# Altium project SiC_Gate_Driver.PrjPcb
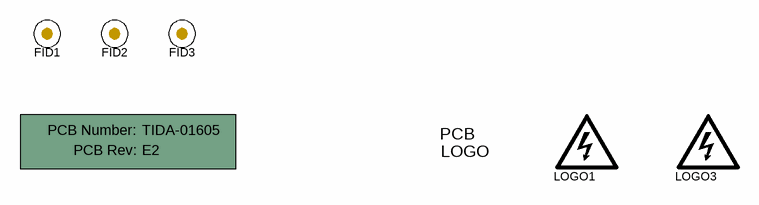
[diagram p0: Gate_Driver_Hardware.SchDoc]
CopyrightYear: 2019; PCB_Layout: X.Gong; PCB_Rev: E2; PRJ_Customer: Public Release; PRJ_Engineer: X.Gong; PRJ_Number: TIDA-01605; PRJ_Title: Isolated SiC Gate Driver with Soft Turn-off Protection; SCH_Rev: E2; TechSupport: http://www.ti.com/support; TID: TIDA-01605
2 sheets, 112 parts. Net scope: flat (ports and power ports of the same name join across sheets).
Board file: Gate_Driver.PcbDoc
Sheets:
  Gate_Driver_Hardware.SchDoc
  Gate_Driver.SchDoc

## Sheet Gate_Driver_Hardware.SchDoc
size 431 x 279 mm; Date: Not shown in title block; ApprovedBy: Not shown in title block; CheckedBy: Not shown in title block; Author: Not shown in title block; CompanyName: Not shown in title block; DrawnBy: G.Wang; Engineer: Not shown in title block; Organization: Not shown in title block; Address1: Not shown in title block; Address2: Not shown in title block; Address3: Not shown in title block; Address4: Not shown in title block; DocumentNumber: 1; Revision: Use project parameter SCH_Rev; SheetNumber: 3; SheetTotal: 3; PageSetup: Record=PageOptions¦CenterHorizontal=True¦CenterVertical=True¦PrintScale=1.00¦XCorrection=1.00¦YCorrection=1.00¦PrintKind=0¦BorderSize=5000000¦LeftOffset=0¦BottomOffset=0¦Orientation=2¦PaperLength=1000¦PaperWidth=1000¦Scale=100¦PaperSource=15¦PrintQuality=600¦MediaType=1¦DitherType=10¦PaperKind=Letter¦PrintScaleMode=1

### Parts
!PCB  Printed Circuit Board  (value not drawn)  (mechanical)
FID1  Fiducial  [Fiducial10-20]  (value not drawn)
FID2  Fiducial  [Fiducial10-20]  (value not drawn)
FID3  Fiducial  [Fiducial10-20]  (value not drawn)
LOGO1  DANGER HIGH VOLTAGE  [IEC_HighVoltage_Small]  (value not drawn)  (no BOM)
Logo2  Pb-Free Symbol  [Pb-Free_Overlay_Small]  (value not drawn)  (no BOM)
LOGO3  DANGER HIGH VOLTAGE  [IEC_HighVoltage_Small]  (value not drawn)  (no BOM)

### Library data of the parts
!PCB = PCB: Manufacturer: Any; PartNumber: TIDA-01605; SymbolCreator: a0412235
FID1-FID3 = Fiducial: Fiducial mark.  There is nothing to buy or mount.; SymbolCreator: codlsc
LOGO1 LOGO3 = IEC_HighVoltage: IEC 61010-1 High Voltage Warning; SymbolCreator: a0412235
Logo2 = Pb-Free: SymbolCreator: a0412235

## Sheet Gate_Driver.SchDoc
size 431 x 279 mm; Date: Not shown in title block; ApprovedBy: Not shown in title block; CheckedBy: Not shown in title block; Author: Not shown in title block; CompanyName: Not shown in title block; DrawnBy: G. Wang; Engineer: Not shown in title block; Organization: Not shown in title block; Address1: Not shown in title block; Address2: Not shown in title block; Address3: Not shown in title block; Address4: Not shown in title block; DocumentNumber: 1; Revision: Use project parameter SCH_Rev; SheetNumber: 2; SheetTotal: 3; PageSetup: Record=PageOptions¦CenterHorizontal=True¦CenterVertical=True¦PrintScale=1.00¦XCorrection=1.00¦YCorrection=1.00¦PrintKind=0¦BorderSize=5000000¦LeftOffset=0¦BottomOffset=0¦Orientation=2¦PaperLength=1000¦PaperWidth=1000¦Scale=100¦PaperSource=15¦PrintQuality=600¦MediaType=1¦DitherType=10¦PaperKind=Letter¦PrintScaleMode=1
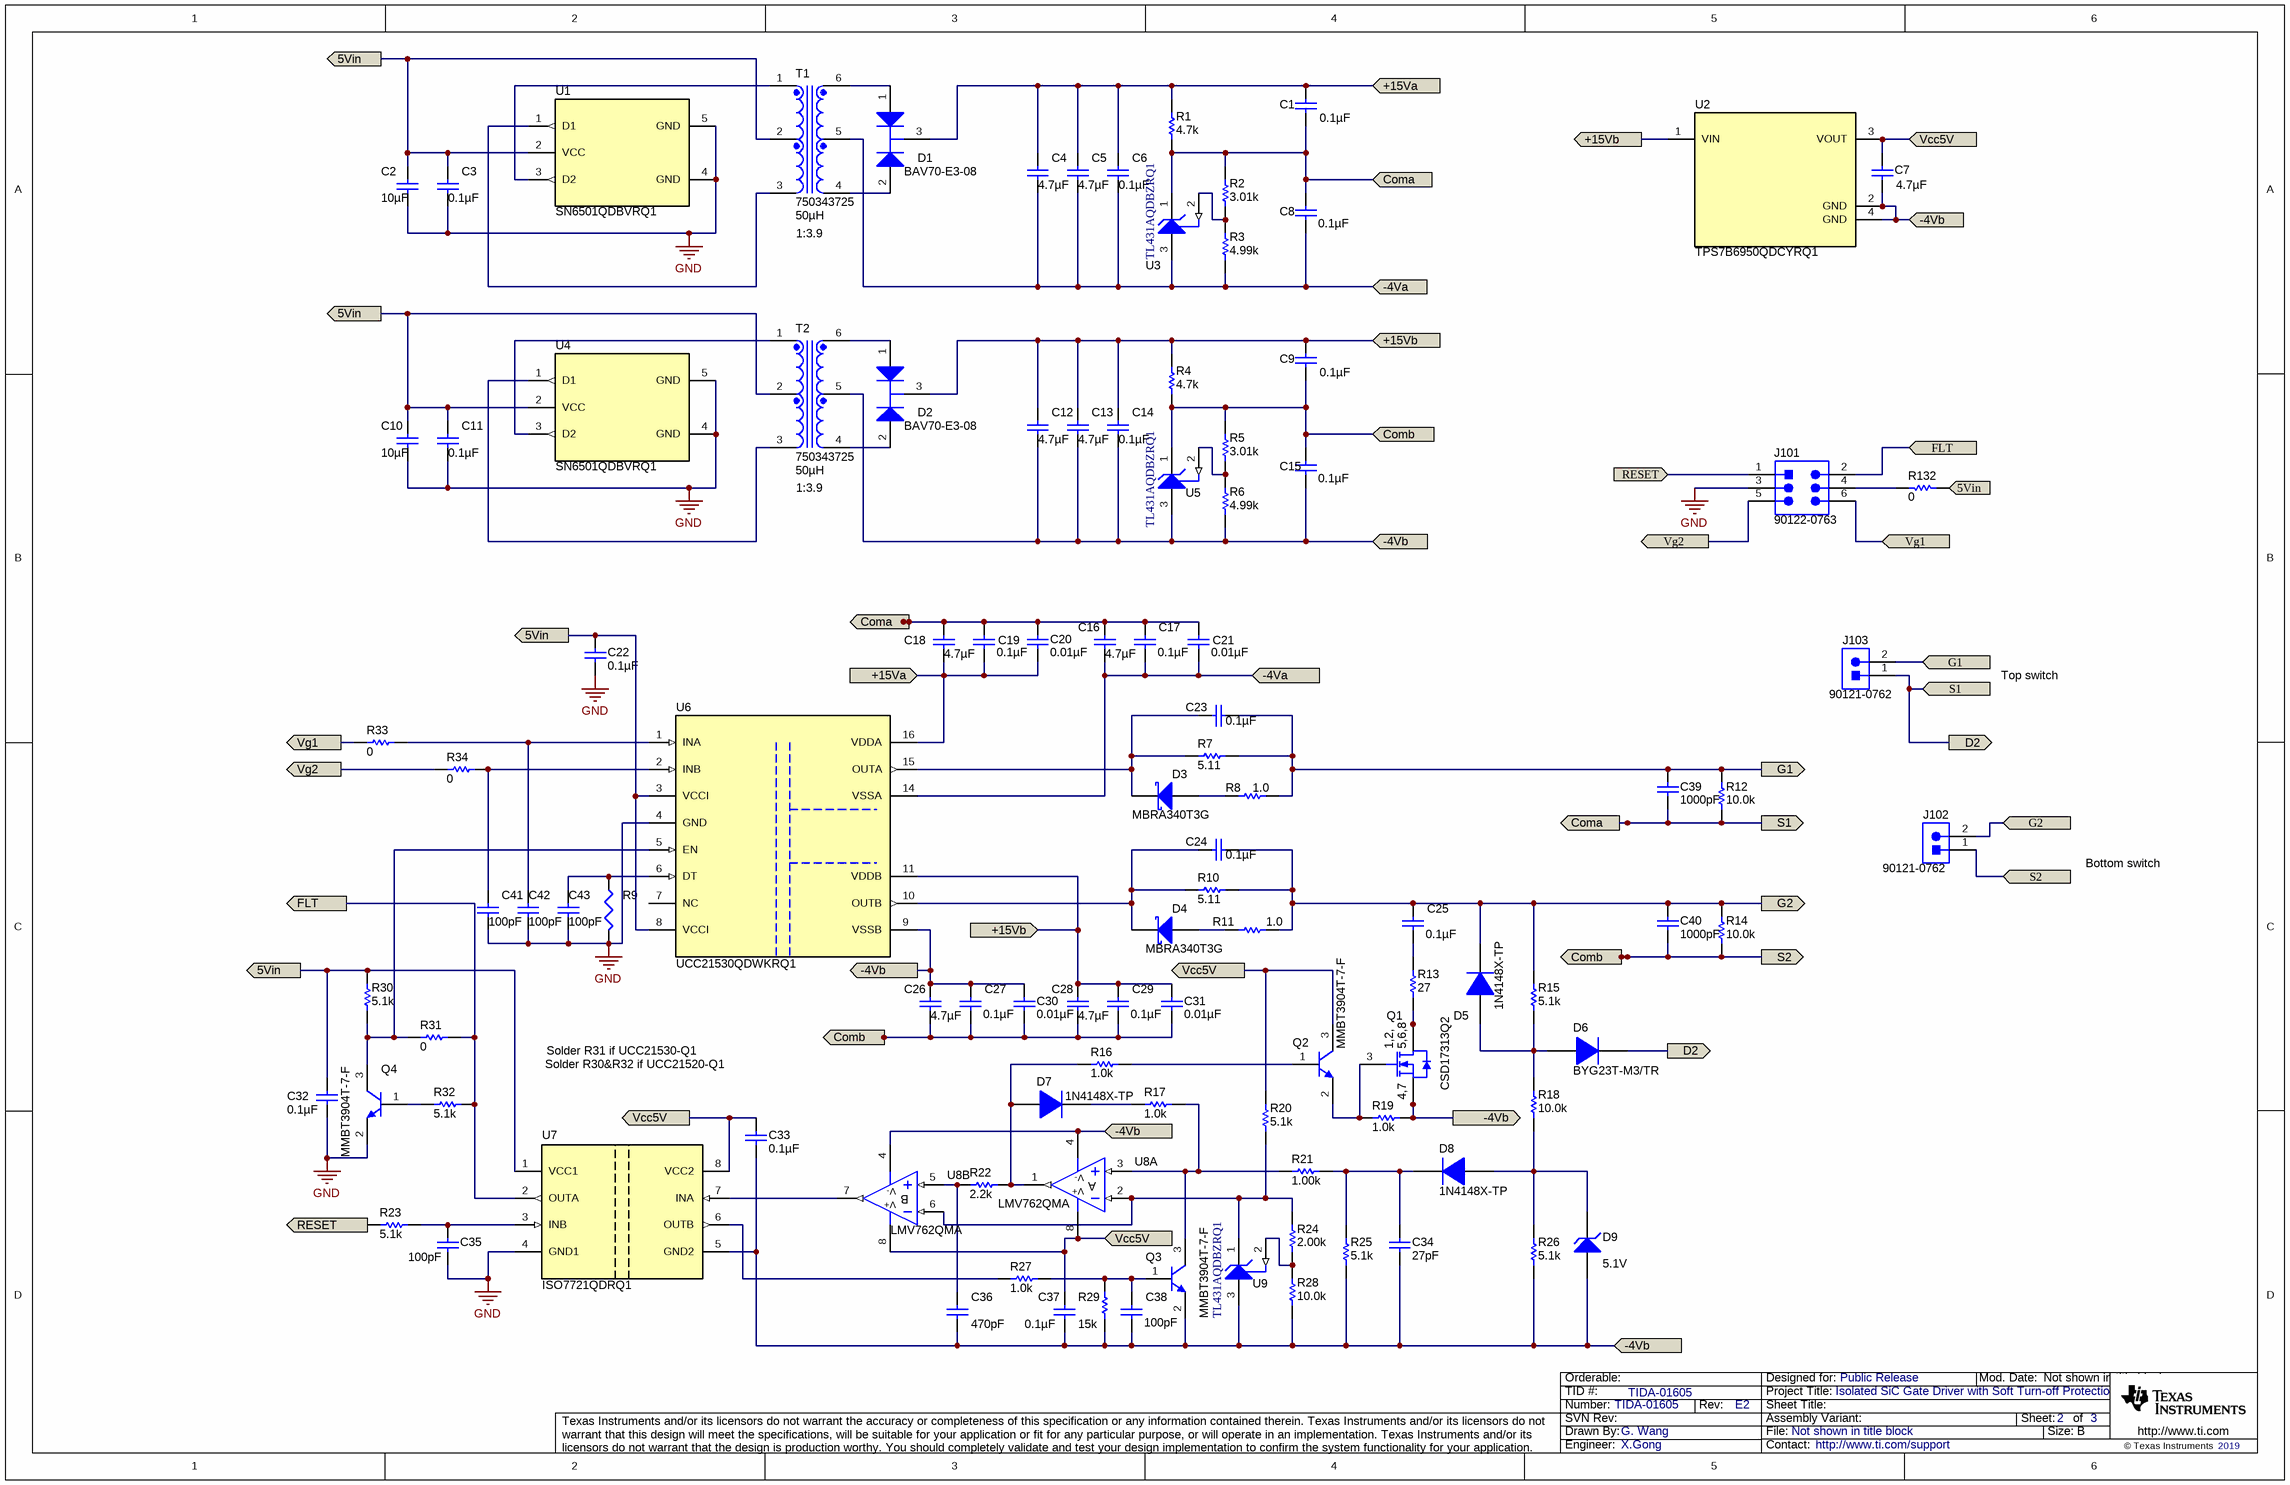
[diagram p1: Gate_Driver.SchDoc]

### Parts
C1  ValueDisplayed: 0.1µF  [0603]  (hidden comment: CGA3E2X7R1E104K080AA)
C2  ValueDisplayed: 10µF  [0603]  (hidden comment: GRT188C81A106ME13D)
C3  ValueDisplayed: 0.1µF  [0603]  (hidden comment: CGA3E2X7R1E104K080AA)
C4  ValueDisplayed: 4.7µF  [0805_HV]  (hidden comment: GRT21BR61H475KE13L)
C5  ValueDisplayed: 4.7µF  [0805_HV]  (hidden comment: GRT21BR61H475KE13L)
C6  ValueDisplayed: 0.1µF  [0603]  (hidden comment: CGA3E2X7R1E104K080AA)
C7  ValueDisplayed: 4.7µF  [0805_HV]  (hidden comment: GRT21BR61H475KE13L)
C8  ValueDisplayed: 0.1µF  [0603]  (hidden comment: CGA3E2X7R1E104K080AA)
C9  ValueDisplayed: 0.1µF  [0603]  (hidden comment: CGA3E2X7R1E104K080AA)
C10  ValueDisplayed: 10µF  [0603]  (hidden comment: GRT188C81A106ME13D)
C11  ValueDisplayed: 0.1µF  [0603]  (hidden comment: CGA3E2X7R1E104K080AA)
C12  ValueDisplayed: 4.7µF  [0805_HV]  (hidden comment: GRT21BR61H475KE13L)
C13  ValueDisplayed: 4.7µF  [0805_HV]  (hidden comment: GRT21BR61H475KE13L)
C14  ValueDisplayed: 0.1µF  [0603]  (hidden comment: CGA3E2X7R1E104K080AA)
C15  ValueDisplayed: 0.1µF  [0603]  (hidden comment: CGA3E2X7R1E104K080AA)
C16  ValueDisplayed: 4.7µF  [0805_HV]  (hidden comment: GRT21BR61H475KE13L)
C17  ValueDisplayed: 0.1µF  [0603]  (hidden comment: CGA3E2X7R1E104K080AA)
C18  ValueDisplayed: 4.7µF  [0805_HV]  (hidden comment: GRT21BR61H475KE13L)
C19  ValueDisplayed: 0.1µF  [0603]  (hidden comment: CGA3E2X7R1E104K080AA)
C20  ValueDisplayed: 0.01µF  [0603]  (hidden comment: CGA3E2C0G1H103J080AA)
C21  ValueDisplayed: 0.01µF  [0603]  (hidden comment: CGA3E2C0G1H103J080AA)
C22  ValueDisplayed: 0.1µF  [0603]  (hidden comment: CGA3E2X7R1E104K080AA)
C23  ValueDisplayed: 0.1µF  [0603]  (hidden comment: CGA3E2X7R1E104K080AA)
C24  ValueDisplayed: 0.1µF  [0603]  (hidden comment: CGA3E2X7R1E104K080AA)
C25  ValueDisplayed: 0.1µF  [0603]  (hidden comment: CGA3E2X7R1E104K080AA)
C26  ValueDisplayed: 4.7µF  [0805_HV]  (hidden comment: GRT21BR61H475KE13L)
C27  ValueDisplayed: 0.1µF  [0603]  (hidden comment: CGA3E2X7R1E104K080AA)
C28  ValueDisplayed: 4.7µF  [0805_HV]  (hidden comment: GRT21BR61H475KE13L)
C29  ValueDisplayed: 0.1µF  [0603]  (hidden comment: CGA3E2X7R1E104K080AA)
C30  ValueDisplayed: 0.01µF  [0603]  (hidden comment: CGA3E2C0G1H103J080AA)
C31  ValueDisplayed: 0.01µF  [0603]  (hidden comment: CGA3E2C0G1H103J080AA)
C32  ValueDisplayed: 0.1µF  [0603]  (hidden comment: CGA3E2X7R1E104K080AA)
C33  ValueDisplayed: 0.1µF  [0603]  (hidden comment: CGA3E2X7R1E104K080AA)
C34  ValueDisplayed: 27pF  [0402]  (hidden comment: GRM1555C1H270JA01D)
C35  ValueDisplayed: 100pF  [0603]  (hidden comment: CGA3E2NP01H101J080AA)
C36  ValueDisplayed: 470pF  [0603]  (hidden comment: GCM1885C1H471JA16D)
C37  ValueDisplayed: 0.1µF  [0603]  (hidden comment: CGA3E2X7R1E104K080AA)
C38  ValueDisplayed: 100pF  [0603]  (hidden comment: GCM1885C2A101JA16D)
C39  ValueDisplayed: 1000pF  [0402]  (hidden comment: GCM155R71H102KA37D)
C40  ValueDisplayed: 1000pF  [0402]  (hidden comment: GCM155R71H102KA37D)
C41  ValueDisplayed: 100pF  [0603]  (hidden comment: GCM1885C2A101JA16D)
C42  ValueDisplayed: 100pF  [0603]  (hidden comment: GCM1885C2A101JA16D)
C43  ValueDisplayed: 100pF  [0603]  (hidden comment: GCM1885C2A101JA16D)
D1  BAV70-E3-08  [SOT-23]
D2  BAV70-E3-08  [SOT-23]
D3  MBRA340T3G  [SMA]
D4  MBRA340T3G  [SMA]
D5  1N4148X-TP  [SOD-523]
D6  BYG23T-M3/TR  [SMA]
D7  1N4148X-TP  [SOD-523]
D8  1N4148X-TP  [SOD-523]
D9  value 5.1V  [SOD-123]  (hidden comment: BZT52C5V1-G3-08)
J101  90122-0763  [Molex_90122-0763]
J102  90121-0762  [Molex_90121-0762]
J103  90121-0762  [Molex_90121-0762]
Q1  CSD17313Q2  [DQK0006C]
Q2  MMBT3904T-7-F  [SOT-523]
Q3  MMBT3904T-7-F  [SOT-523]
Q4  MMBT3904T-7-F  [SOT-523]
R1  ValueDisplayed: 4.7k  [0805_HV]  (hidden comment: CRCW08054K70JNEA)
R2  ValueDisplayed: 3.01k  [0603]  (hidden comment: RT0603DRE073K01L)
R3  ValueDisplayed: 4.99k  [0603]  (hidden comment: RT0603DRE074K99L)
R4  ValueDisplayed: 4.7k  [0805_HV]  (hidden comment: CRCW08054K70JNEA)
R5  ValueDisplayed: 3.01k  [0603]  (hidden comment: RT0603DRE073K01L)
R6  ValueDisplayed: 4.99k  [0603]  (hidden comment: RT0603DRE074K99L)
R7  ValueDisplayed: 5.11  [1206]  (hidden comment: CRCW12065R11FKEA)
R8  ValueDisplayed: 1.0  [1206]  (hidden comment: CRM1206-JW-1R0ELF)
R9  1  [J1-0603]  (value not drawn)
R10  ValueDisplayed: 5.11  [1206]  (hidden comment: CRCW12065R11FKEA)
R11  ValueDisplayed: 1.0  [1206]  (hidden comment: CRM1206-JW-1R0ELF)
R12  ValueDisplayed: 10.0k  [0603]  (hidden comment: CRCW060310K0FKEA)
R13  ValueDisplayed: 27  [1206]  (hidden comment: CRCW120627R0JNEA)
R14  ValueDisplayed: 10.0k  [0603]  (hidden comment: CRCW060310K0FKEA)
R15  ValueDisplayed: 5.1k  [0603]  (hidden comment: RC0603JR-075K1L)
R16  ValueDisplayed: 1.0k  [0603]  (hidden comment: RCA06031K00JNEA)
R17  ValueDisplayed: 1.0k  [0603]  (hidden comment: RCA06031K00JNEA)
R18  ValueDisplayed: 10.0k  [TNPW0603]  (hidden comment: TNPW060310K0BEEA)
R19  ValueDisplayed: 1.0k  [0603]  (hidden comment: RCA06031K00JNEA)
R20  ValueDisplayed: 5.1k  [0603]  (hidden comment: RC0603JR-075K1L)
R21  ValueDisplayed: 1.00k  [0603]  (hidden comment: CRCW06031K00FKEA)
R22  ValueDisplayed: 2.2k  [0603]  (hidden comment: RC0603JR-072K2L)
R23  ValueDisplayed: 5.1k  [0603]  (hidden comment: RC0603JR-075K1L)
R24  ValueDisplayed: 2.00k  [0603]  (hidden comment: RT0603DRE072KL)
R25  ValueDisplayed: 5.1k  [0603]  (hidden comment: RC0603JR-075K1L)
R26  ValueDisplayed: 5.1k  [0603]  (hidden comment: RC0603JR-075K1L)
R27  ValueDisplayed: 1.0k  [0603]  (hidden comment: RCA06031K00JNEA)
R28  ValueDisplayed: 10.0k  [0603]  (hidden comment: RT0603DRE0710KL)
R29  ValueDisplayed: 15k  [0603]  (hidden comment: RC0603JR-0715KL)
R30  ValueDisplayed: 5.1k  [0603]  (hidden comment: RC0603JR-075K1L)
R31  ValueDisplayed: 0  [0603]  (hidden comment: CRCW06030000Z0EA)
R32  ValueDisplayed: 5.1k  [0603]  (hidden comment: RC0603JR-075K1L)
R33  ValueDisplayed: 0  [0603]  (hidden comment: CRCW06030000Z0EA)
R34  ValueDisplayed: 0  [0603]  (hidden comment: CRCW06030000Z0EA)
R132  ValueDisplayed: 0  [0603]  (hidden comment: CRCW06030000Z0EA)
T1  PartNumber: 750343725  ValueDisplayed: 50µH  [Wurth_750342879]  (hidden comment: 3.9:1)
T2  PartNumber: 750343725  ValueDisplayed: 50µH  [Wurth_750342879]  (hidden comment: 3.9:1)
U1  SN6501QDBVRQ1  [DBV0005A_N]
U2  TPS7B6950QDCYRQ1  [DCY0004A_N]
U3  TL431AQDBZRQ1  [DBZ0003A_N]
U4  SN6501QDBVRQ1  [DBV0005A_N]
U5  TL431AQDBZRQ1  [DBZ0003A_N]
U6  UCC21530QDWKRQ1  [DWK0014A]
U7  ISO7721QDRQ1  [D0008B_HV]
U8  LMV762QMA  [D0008A_N]  (parts A,B of 2)
U9  TL431AQDBZRQ1  [DBZ0003A_N]

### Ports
5Vin, +15Va, +15Vb, -4Va, -4Vb, Coma, Comb, D2, FLT, G1, G2, RESET, S1, S2, Vcc5V, Vg1, Vg2

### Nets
GND: C2.2 C3.2 C10.2 C11.2 C22.2 C32.2 C35.2 C41.2 C42.2 C43.2 J101.3 Q4.2(E) R9.2 U1.4(GND) U1.5(GND) U4.4(GND) U4.5(GND) U6.4(GND) U7.4(GND1)
5Vin: C2.1 C3.1 C10.1 C11.1 C22.1 C32.1 R30.2 R132.2 T1.2 T2.2 U1.2(VCC) U4.2(VCC) U6.3(VCCI) U6.8(VCCI) U7.1(VCC1) ; port 5Vin
+15Va: C1.1 C4.1 C5.1 C6.1 C18.2 C19.2 C20.2 D1.3(C) R1.2 U6.16(VDDA) ; port +15Va
+15Vb: C9.1 C12.1 C13.1 C14.1 C28.1 C29.1 C31.1 D2.3(C) R4.2 U2.1(VIN) U6.11(VDDB) ; port +15Vb
-4Va: C4.2 C5.2 C6.2 C8.2 C16.2 C17.2 C21.2 R3.1 T1.5 U3.3(ANODE) U6.14(VSSA) ; port -4Va
-4Vb: C7.2 C12.2 C13.2 C14.2 C15.2 C26.1 C27.1 C30.1 C33.2 C34.2 C36.2 C37.2 C38.2 D9.2(A) Q1.4(S) Q1.7(S) Q3.2(E) R6.1 R19.2 R25.1 R26.1 R28.1 R29.1 T2.5 U2.2(GND) U2.4(GND) U5.3(ANODE) U6.9(VSSB) U7.5(GND2) U8.4(V-) U9.3(ANODE) ; port -4Vb
Coma: C1.2 C8.1 C16.1 C17.1 C18.1 C19.1 C20.1 C21.1 C39.2 D6.1(K) J103.1 R1.1 R2.2 R12.1 U3.1(CATHODE) ; port D2, port Coma, port S1
Comb: C9.2 C15.1 C26.2 C27.2 C28.2 C29.2 C30.2 C31.2 C40.2 J102.1 R4.1 R5.2 R14.1 U5.1(CATHODE) ; port Comb, port S2
FLT: J101.2 R31.1 R32.2 U7.2(OUTA) ; port FLT
G1: C23.2 C39.1 J103.2 R7.2 R8.2 R12.2 ; port G1
G2: C24.2 C25.1 C40.1 D5.1(K) J102.2 R10.2 R11.2 R14.2 R15.2 ; port G2
RESET: J101.1 R23.1 ; port RESET
Vcc5V: C7.1 C33.1 C37.1 Q2.3(C) R20.2 U2.3(VOUT) U7.8(VCC2) U8.8(V+) ; port Vcc5V
Vg1: J101.6 R33.2 ; port Vg1
Vg2: J101.5 R34.2 ; port Vg2
NetC23_1: C23.1 D3.1(K) R7.1 U6.15(OUTA)
NetC24_1: C24.1 D4.1(K) R10.1 U6.10(OUTB)
NetC25_2: C25.2 R13.2
NetC34_1: C34.1 D8.1(K) R21.2 R25.2
NetC35_1: C35.1 R23.2 U7.3(INB)
NetC36_1: C36.1 R22.2 U8.5(IN+)
NetC38_1: C38.1 Q3.1(B) R27.2 R29.2
NetC41_1: C41.1 R34.1 U6.2(INB)
NetC42_1: C42.1 R33.1 U6.1(INA)
NetC43_1: C43.1 R9.1 U6.6(DT)
NetD1_1: D1.1(A) T1.6
NetD1_2: D1.2(K) T1.4
NetD2_1: D2.1(A) T2.6
NetD2_2: D2.2(K) T2.4
NetD3_2: D3.2(A) R8.1
NetD4_2: D4.2(A) R11.1
NetD5_2: D5.2(A) D6.2(A) R15.1 R18.2
NetD7_1: D7.1(K) R17.1
NetD7_2: D7.2(A) R16.1 R22.1 U8.1(OUT)
NetD8_2: D8.2(A) D9.1(K) R18.1 R26.2
NetJ101_4: J101.4 R132.1
NetQ1_1: Q1.1(D) Q1.2(D) Q1.5(D) Q1.6(D) Q1.8(D) R13.1
NetQ1_3: Q1.3(G) Q2.2(E) R19.1
NetQ2_1: Q2.1(B) R16.2
NetQ3_3: Q3.3(C) R17.2 R21.1 U8.3(IN+)
NetQ4_1: Q4.1(B) R32.1
NetQ4_3: Q4.3(C) R30.1 R31.2 U6.5(EN)
NetR2_1: R2.1 R3.2 U3.2(REF)
NetR5_1: R5.1 R6.2 U5.2(REF)
NetR20_1: R20.1 R24.2 U8.2(IN-) U8.6(IN-) U9.1(CATHODE)
NetR24_1: R24.1 R28.2 U9.2(REF)
NetR27_1: R27.1 U7.6(OUTB)
NetT1_1: T1.1 U1.3(D2)
NetT1_3: T1.3 U1.1(D1)
NetT2_1: T2.1 U4.3(D2)
NetT2_3: T2.3 U4.1(D1)
NetU7_7: U7.7(INA) U8.7(OUT)

Not connected (* = marked no-connect by the designer): U6 7(NC)

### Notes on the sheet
- (near T1) 1:3.9
- (near T2) 1:3.9
- Top switch
- Bottom switch
- Solder R31 if UCC21530-Q1
- Solder R30&R32 if UCC21520-Q1

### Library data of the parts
C1 C3 C6 C8 C9 C11 C14 C15 C17 C19 C22-C25 C27 C29 C32 C33 C37 = CGA3E2X7R1E104K080AA: CAP, CERM, 0.1 µF, 25 V,+/- 10%, X7R, AEC-Q200 Grade 1, 0603; Manufacturer: TDK; Polarized: N; CompType: Capacitor; Value: 0.1uF; U/M: EA; Cap_F: 0.0000001; Tolerance_%: 10; VDC_V: 25; Value2: 25V; TaMin_C: -55; TaMax_C: 125; SizeArea_mm2: 1.28; SizeAreaWB_mm2: 4.68; SizeX_mm: 1.6; SizeY_mm: 0.8; SizeZ_mm: 1; AEC Category: Q200; AEC Qualified: Y
C2 C10 = GRT188C81A106ME13D: CAP, CERM, 10 µF, 10 V,+/- 20%, X6S, AEC-Q200 Grade 2, 0603; Manufacturer: MuRata; Polarized: N; CompType: Capacitor; Value: 10uF; U/M: EA; Cap_F: 0.00001; Tolerance_%: 20; VDC_V: 10; Value2: 10V; TaMin_C: -55; TaMax_C: 105; SizeArea_mm2: 1.28; SizeAreaWB_mm2: 4.68; SizeX_mm: 1.6; SizeY_mm: 0.8; SizeZ_mm: 1; AEC Category: Q200; AEC Qualified: Y; AEC Grade: 2; Green_Lifecycle: Active; Green_REACh: Passed
C4 C5 C7 C12 C13 C16 C18 C26 C28 = GRT21BR61H475KE13L: CAP, CERM, 4.7 µF, 50 V,+/- 10%, X5R, AEC-Q200 Grade 3, 0805; Manufacturer: MuRata; Polarized: N; CompType: Capacitor; Value: 4.7uF; U/M: EA; Cap_F: 0.0000047; Tolerance_%: 10; VDC_V: 50; Value2: 50V; TaMin_C: -55; TaMax_C: 85; Cap_Case: 0805; SizeArea_mm2: 2.5; SizeAreaWB_mm2: 6.75; SizeX_mm: 2; SizeY_mm: 1.25; SizeZ_mm: 1.45; AEC Category: Q200; AEC Qualified: Y; AEC Grade: 3
C20 C21 C30 C31 = CGA3E2C0G1H103J080AA: CAP, CERM, 0.01 µF, 50 V,+/- 5%, C0G/NP0, AEC-Q200 Grade 1, 0603; Manufacturer: TDK; Polarized: N; CompType: Capacitor; Value: 0.01uF; U/M: EA; Cap_F: 0.00000001; Tolerance_%: 5; VDC_V: 50; Value2: 50V; TaMin_C: -55; TaMax_C: 125; SizeArea_mm2: 1.28; SizeAreaWB_mm2: 4.68; SizeX_mm: 1.6; SizeY_mm: 0.8; SizeZ_mm: 1; AEC Category: Q200; AEC Qualified: Y; Green_Lifecycle: Active; Green_REACh: Passed
C34 = GRM1555C1H270JA01D: CAP, CERM, 27 pF, 50 V,+/- 5%, C0G/NP0, 0402; Manufacturer: MuRata; Polarized: N; CompType: Capacitor; Value: 27pF; U/M: EA; Cap_F: 0.000000000027; Tolerance_%: 5; VDC_V: 50; Value2: 50V; TaMin_C: -55; TaMax_C: 125; SizeArea_mm2: 0.5; SizeAreaWB_mm2: 3; SizeX_mm: 1; SizeZ_mm: 0.6; AEC Category: Q200; Green_Lifecycle: Active; Green_REACh: Passed
C35 = CGA3E2NP01H101J080AA: CAP, CERM, 100 pF, 50 V,+/- 5%, C0G/NP0, AEC-Q200 Grade 0, 0603; Manufacturer: TDK; Polarized: N; CompType: Capacitor; Value: 100pF; U/M: EA; Cap_F: 0.0000000001; Tolerance_%: 5; VDC_V: 50; Value2: 50V; TaMin_C: -55; TaMax_C: 150; SizeArea_mm2: 1.28; SizeAreaWB_mm2: 4.68; SizeX_mm: 1.6; SizeY_mm: 0.8; SizeZ_mm: 1; AEC Category: Q200; AEC Qualified: Y; AEC Grade: 0; Green_Lifecycle: Active; Green_REACh: Passed
C36 = GCM1885C1H471JA16D: CAP, CERM, 470 pF, 50 V,+/- 5%, C0G/NP0, AEC-Q200 Grade 1, 0603; Manufacturer: MuRata; Polarized: N; CompType: Capacitor; Value: 470pF; U/M: EA; Cap_F: 0.00000000047; Tolerance_%: 5; VDC_V: 50; Value2: 50V; TaMin_C: -55; TaMax_C: 125; SizeArea_mm2: 1.28; SizeAreaWB_mm2: 4.68; SizeX_mm: 1.6; SizeY_mm: 0.8; SizeZ_mm: 1; AEC Category: Q200; AEC Qualified: Y; Green_Lifecycle: Active; Green_REACh: Passed
C38 C41-C43 = GCM1885C2A101JA16D: CAP, CERM, 100 pF, 100 V,+/- 5%, C0G/NP0, AEC-Q200 Grade 1, 0603; Manufacturer: MuRata; Polarized: N; CompType: Capacitor; Value: 100pF; U/M: EA; Cap_F: 0.0000000001; Tolerance_%: 5; VDC_V: 100; Value2: 100V; TaMin_C: -55; TaMax_C: 125; SizeArea_mm2: 1.28; SizeAreaWB_mm2: 4.68; SizeX_mm: 1.6; SizeY_mm: 0.8; SizeZ_mm: 1; AEC Category: Q200; AEC Qualified: Y
C39 C40 = GCM155R71H102KA37D: CAP, CERM, 1000 pF, 50 V,+/- 10%, X7R, AEC-Q200 Grade 1, 0402; Manufacturer: MuRata; Polarized: N; CompType: Capacitor; Value: 1000pF; U/M: EA; Cap_F: 0.000000001; Tolerance_%: 10; VDC_V: 50; Value2: 50V; TaMin_C: -55; TaMax_C: 125; SizeArea_mm2: 0.5; SizeAreaWB_mm2: 3; SizeX_mm: 1; SizeZ_mm: 0.6; AEC Category: Q200; AEC Qualified: Y
D1 D2 = BAV70-E3-08: Diode, Switching, 70 V, 0.25 A, AEC-Q101, SOT-23; Manufacturer: Vishay-Semiconductor; SymbolCreator: a0412235; U/M: EA; Vf_V: 1.25; Value: 70V; Value1: 0.25A; Value2: 1.25V; Io_A: 0.25; Vr_V: 70; TJmax_C: 150; SizeAreaWB_mm2: 14; SizeArea_mm2: 7.5; SizeX_mm: 2.5; SizeY_mm: 3; SizeZ_mm: 1.1; AEC Category: Q101; AEC Qualified: Y; Green_Lifecycle: Not Set; Green_REACh: Incomplete
D3 D4 = MBRA340T3G: Diode, Schottky, 40 V, 3 A, SMA; Manufacturer: ON Semiconductor; U/M: EA; Vf_V: 0.415; Value: 40V; Value1: 3A; Value2: 0.415V; Io_A: 3; Vr_V: 40; RJC_CperW: 15; SizeAreaWB_mm2: 37.3428; SizeArea_mm2: 16.3228; SizeX_mm: 5.59; SizeY_mm: 2.92; SizeZ_mm: 2.87; AEC Category: Q101; Green_Lifecycle: Not Set; Green_REACh: Incomplete
D5 D7 D8 = 1N4148X-TP: Diode, Switching, 75 V, 0.3 A, SOD-523; Manufacturer: Micro Commercial Components; U/M: EA; Vf_V: 1.25; Value: 75V; Value1: 0.3A; Value2: 1.25V; Io_A: 0.3; Vr_V: 75; TJmax_C: 150; SizeAreaWB_mm2: 5.13; SizeArea_mm2: 1.53; SizeX_mm: 1.7; SizeY_mm: 0.9; SizeZ_mm: 0.65; AEC Category: Q101; Green_Lifecycle: Not Set; Green_REACh: Incomplete
D6 = CMP-0077058-1: Diode, Ultrafast, 1300 V, 1 A, SMA; Manufacturer: Vishay-Semiconductor; SizeAreaWB_mm2: 37.3428; Vr_V: 1.3kV; SizeArea_mm2: 16.3228; AEC Qualified: N; TJmax_C: 150°C; AEC Category: Q101; Value: 1300V; SizeZ_mm: 2.87; Green_REACh: Incomplete; Io_A: 1A; Vf_V: 1.9V; SizeY_mm: 2.92; Green_Lifecycle: Not Set; U/M: EA; SizeX_mm: 5.59
D9 = BZT52C5V1-G3-08: Diode, Zener, 5.1 V, 500 mW, SOD-123; Manufacturer: Vishay-Semiconductor; SymbolCreator: a0412235; U/M: EA; Power_W: 0.5; Vz_V: 5.1; Value1: 0.5W; RJA_CperW: 300; SizeAreaWB_mm2: 13.095; SizeArea_mm2: 6.545; SizeX_mm: 3.85; SizeY_mm: 1.7; SizeZ_mm: 1.35; AEC Category: Q101
J101 = CMP-0077741-1: Header, 2.54mm, 3x2, Gold, R/A, TH; Manufacturer: Molex; Pitch_mm: 2.54; Gender: Male; Cert_UL: Y; Current_A: 3A; Voltage_V: 350V; Shrouded: N; Row_Count: 2
J102 J103 = CMP-0077745-1: Header, 2.54mm, 2x1, Gold with Tin tail, R/A, TH; Manufacturer: Molex; Pitch_mm: 2.54; Gender: Male; Cert_UL: Y; Current_A: 3A; Voltage_V: 350V; Shrouded: N; Row_Count: 1
Q1 = CSD17313Q2: MOSFET, N-CH, 30 V, 5 A, DQK0006C (WSON-6); Manufacturer: Texas Instruments; Alternate Manufacturer: None; U/M: EA; ChType: N; Value: 30V; VdsMax_V: 30; Value1: 0.026 ohm; Rdson45_ohm: 0.026; Value2: 2.1 nC; QgTyp_nC: 2.1; Vgs_V: 10; IdsMax_A: 5; SizeAreaWB_mm2: 9; SizeArea_mm2: 4; SizeX_mm: 2; SizeZ_mm: 0.8; AEC Category: Q101
Q2-Q4 = MMBT3904T-7-F, Diodes Inc.: Transistor, NPN, 40 V, 0.2 A, SOT-523; CompType: BJT; PNP: 0; NPN: 1; Vceo_V: 40; Vcesat1_V: 0.2; Value: 40 V; Value1: 0.2 A; HfeMax: 300; TaMin_C: -55; TaMax_C: 150; SizeAreaWB_mm2: 6.76; SizeArea_mm2: 2.56; SizeX_mm: 1.6; SizeZ_mm: 0.8; U/M: EA; AEC Category: Q101; Green_Lifecycle: Active; Green_REACh: Passed
R1 R4 = CRCW08054K70JNEA: RES, 4.7 k, 5%, 0.125 W, 0805; Manufacturer: Vishay-Dale; CompType: Resistor; Value: 4.7k; Res_ohm: 4700; Value_Code: 4k70; Tolerance_%: 5; Power_W: 0.125; Value2: 0.125W; VDC_V: 150; TempCo: 200 ppm/C; SizeArea_mm2: 2.5; SizeX_mm: 2; SizeY_mm: 1.25; SizeZ_mm: 1.45; EIA_Code: E24; U/M: EA; AEC Category: Q200; Green_Lifecycle: Active; Green_REACh: Passed
R2 R5 = RT0603DRE073K01L: RES, 3.01 k, 0.5%, 0.1 W, 0603; Manufacturer: Yageo America; CompType: Resistor; Value: 3.01k; Res_ohm: 3010; Value_Code: 3k01; Tolerance_%: 0.5; Power_W: 0.1; Value2: 0.1W; VDC_V: 75; TempCo: 50 ppm/C; SizeArea_mm2: 1.28; SizeX_mm: 1.6; SizeY_mm: 0.8; SizeZ_mm: 1; EIA_Code: E192; U/M: EA; AEC Category: Q200
R3 R6 = RT0603DRE074K99L: RES, 4.99 k, 0.5%, 0.1 W, 0603; Manufacturer: Yageo America; CompType: Resistor; Value: 4.99k; Res_ohm: 4990; Value_Code: 4k99; Tolerance_%: 0.5; Power_W: 0.1; Value2: 0.1W; VDC_V: 75; TempCo: 50 ppm/C; SizeArea_mm2: 1.28; SizeX_mm: 1.6; SizeY_mm: 0.8; SizeZ_mm: 1; EIA_Code: E192; U/M: EA; AEC Category: Q200; Green_Lifecycle: Active; Green_REACh: Passed
R7 R10 = CRCW12065R11FKEA: RES, 5.11, 1%, 0.25 W, 1206; Manufacturer: Vishay-Dale; CompType: Resistor; Value: 5.11; Value_Code: 5R11; Tolerance_%: 1; Power_W: 0.25; Value2: 0.25W; VDC_V: 200; TempCo: 100 ppm/C; SizeArea_mm2: 5.12; SizeX_mm: 3.2; SizeY_mm: 1.6; SizeZ_mm: 1.35; EIA_Code: E96; U/M: EA; AEC Category: Q200
R8 R11 = CRM1206-JW-1R0ELF: RES, 1.0, 5%, 0.5 W, 1206; Manufacturer: Bourns; CompType: Resistor; Value: 1.0; Res_ohm: 1; Value_Code: 1R00; Tolerance_%: 5; Power_W: 0.5; Value2: 0.5W; TempCo: 150 ppm/C; SizeArea_mm2: 5.12; SizeX_mm: 3.2; SizeY_mm: 1.6; SizeZ_mm: 1.35; EIA_Code: E24; U/M: EA; AEC Category: Q200
R9 = Res3: Resistor
R12 R14 = CRCW060310K0FKEA: RES, 10.0 k, 1%, 0.1 W, 0603; Manufacturer: Vishay-Dale; CompType: Resistor; Value: 10.0k; Res_ohm: 10000; Value_Code: 10k0; Tolerance_%: 1; Power_W: 0.1; Value2: 0.1W; VDC_V: 75; TempCo: 100 ppm/C; SizeArea_mm2: 1.28; SizeX_mm: 1.6; SizeY_mm: 0.8; EIA_Code: E96; U/M: EA; AEC Category: Q200; Green_Lifecycle: Active; Green_REACh: Passed
R13 = CRCW120627R0JNEA: RES, 27, 5%, 0.25 W, 1206; Manufacturer: Vishay-Dale; CompType: Resistor; Value: 27; Value_Code: 27R0; Tolerance_%: 5; Power_W: 0.25; Value2: 0.25W; VDC_V: 200; TempCo: 200 ppm/C; SizeArea_mm2: 5.12; SizeX_mm: 3.2; SizeY_mm: 1.6; SizeZ_mm: 1.35; EIA_Code: E24; U/M: EA; AEC Category: Q200
R15 R20 R23 R25 R26 R30 R32 = RC0603JR-075K1L: RES, 5.1 k, 5%, 0.1 W, 0603; Manufacturer: Yageo America; CompType: Resistor; Value: 5.1k; Res_ohm: 5100; Value_Code: 5k10; Tolerance_%: 5; Power_W: 0.1; Value2: 0.1W; VDC_V: 50; TempCo: 100 ppm/C; SizeArea_mm2: 1.28; SizeX_mm: 1.6; SizeY_mm: 0.8; SizeZ_mm: 1; EIA_Code: E24; U/M: EA; AEC Category: Q200
R16 R17 R19 R27 = RCA06031K00JNEA: RES, 1.0 k, 5%, 0.1 W, AEC-Q200 Grade 0, 0603; Manufacturer: Vishay-Dale; CompType: Resistor; Value: 1.0k; Res_ohm: 1000; Value_Code: 1k00; Tolerance_%: 5; Power_W: 0.1; Value2: 0.1W; VDC_V: 75; TempCo: 200 ppm/C; SizeArea_mm2: 1.28; SizeX_mm: 1.6; SizeY_mm: 0.8; SizeZ_mm: 1; EIA_Code: E24; U/M: EA; AEC Category: Q200; AEC Qualified: Y; AEC Grade: 0
R18 = TNPW060310K0BEEA: RES, 10.0 k, 0.1%, 0.1 W, AEC-Q200 Grade 1, 0603; Manufacturer: Vishay-Dale; CompType: Resistor; Value: 10.0k; Res_ohm: 10000; Value_Code: 10k0; Tolerance_%: 0.1; Value2: 0.1W; VDC_V: 75; TempCo: 25 ppm/C; SizeArea_mm2: 1.36; SizeX_mm: 1.6; SizeY_mm: 0.85; SizeZ_mm: 0.55; EIA_Code: E192; U/M: EA; AEC Category: Q200; AEC Qualified: Y; AEC Grade: 1
R21 = CRCW06031K00FKEA: RES, 1.00 k, 1%, 0.1 W, 0603; Manufacturer: Vishay-Dale; CompType: Resistor; Value: 1.00k; Res_ohm: 1000; Value_Code: 1k00; Tolerance_%: 1; Power_W: 0.1; Value2: 0.1W; VDC_V: 75; TempCo: 100 ppm/C; SizeArea_mm2: 1.28; SizeX_mm: 1.6; SizeY_mm: 0.8; EIA_Code: E96; U/M: EA; AEC Category: Q200; Green_Lifecycle: Active; Green_REACh: Passed
R22 = RC0603JR-072K2L: RES, 2.2 k, 5%, 0.1 W, 0603; Manufacturer: Yageo America; CompType: Resistor; Value: 2.2k; Res_ohm: 2200; Value_Code: 2k20; Tolerance_%: 5; Power_W: 0.1; Value2: 0.1W; VDC_V: 50; TempCo: 100 ppm/C; SizeArea_mm2: 1.28; SizeX_mm: 1.6; SizeY_mm: 0.8; SizeZ_mm: 1; EIA_Code: E24; U/M: EA; AEC Category: Q200; Green_Lifecycle: Active; Green_REACh: Passed
R24 = RT0603DRE072KL: RES, 2.00 k, 0.5%, 0.1 W, 0603; Manufacturer: Yageo America; CompType: Resistor; Value: 2.00k; Res_ohm: 2000; Value_Code: 2k00; Tolerance_%: 0.5; Power_W: 0.1; Value2: 0.1W; VDC_V: 75; TempCo: 50 ppm/C; SizeArea_mm2: 1.28; SizeX_mm: 1.6; SizeY_mm: 0.8; SizeZ_mm: 1; EIA_Code: E192; U/M: EA; AEC Category: Q200
R28 = RT0603DRE0710KL: RES, 10.0 k, 0.5%, 0.1 W, 0603; Manufacturer: Yageo America; CompType: Resistor; Value: 10.0k; Res_ohm: 10000; Value_Code: 10k0; Tolerance_%: 0.5; Power_W: 0.1; Value2: 0.1W; VDC_V: 75; TempCo: 50 ppm/C; SizeArea_mm2: 1.28; SizeX_mm: 1.6; SizeY_mm: 0.8; SizeZ_mm: 1; EIA_Code: E192; U/M: EA; AEC Category: Q200; Green_Lifecycle: Active; Green_REACh: Passed
R29 = RC0603JR-0715KL: RES, 15 k, 5%, 0.1 W, 0603; Manufacturer: Yageo America; CompType: Resistor; Value: 15k; Res_ohm: 15000; Value_Code: 15k0; Tolerance_%: 5; Power_W: 0.1; Value2: 0.1W; VDC_V: 50; TempCo: 100 ppm/C; SizeArea_mm2: 1.28; SizeX_mm: 1.6; SizeY_mm: 0.8; SizeZ_mm: 1; EIA_Code: E24; U/M: EA; AEC Category: Q200
R31 R33 R34 = CRCW06030000Z0EA: RES, 0, 5%, 0.1 W, 0603; Manufacturer: Vishay-Dale; CompType: Resistor; Value: 0; Value_Code: 0000; Tolerance_%: 5; Power_W: 0.1; Value2: 0.1W; VDC_V: 75; TempCo: 200 ppm/C; SizeArea_mm2: 1.28; SizeX_mm: 1.6; SizeY_mm: 0.8; SizeZ_mm: 1; EIA_Code: E24; U/M: EA; AEC Category: Q200; Green_Lifecycle: Active; Green_REACh: Passed
R132 = CRCW06030000Z0EA: RES, 0, 5%, 0.1 W, 0603; Manufacturer: Vishay-Dale; CompType: Resistor; Value: 0; Value_Code: 0000; Tolerance_%: 5; Power_W: 0.1; Value2: 0.1W; VDC_V: 75; TempCo: 200 ppm/C; SizeArea_mm2: 1.28; SizeX_mm: 1.6; SizeY_mm: 0.8; SizeZ_mm: 1; EIA_Code: E24; U/M: EA; AEC Category: Q200
T1 T2 = 750342879: Transformer, 50 uH, SMT; Manufacturer: Wurth Elektronik; SymbolCreator: Altium; Value: 50uH; Lp: 50; Ind_H: 5E-5
U1 U4 = SN6501QDBVRQ1: Automotive Low-Noise 350 mA, 410 kHz Transformer Driver, DBV0005A (SOT-23-5); Manufacturer: Texas Instruments; SymbolCreator: a0411947; SizeArea_mm2: 8.12; SizeAreaWB_mm2: 14.82; SizeX_mm: 2.8; SizeY_mm: 2.9; SizeZ_mm: 1.45; CompType: IC; U/M: EA
U2 = TPS7B6950QDCYRQ1: Automotive High-Voltage Ultra-Low IQ Low-Dropout Regulator/Fixed 5-V Output Voltage, DCY0004A (SOT-223-4); Manufacturer: Texas Instruments; SymbolCreator: Altium; SizeArea_mm2: 45.5; SizeAreaWB_mm2: 76.5; SizeX_mm: 7; SizeY_mm: 6.5; SizeZ_mm: 1.8; CompType: IC; U/M: EA; Green_Lifecycle: Active; Green_REACh: Passed
U3 U5 U9 = TL431AQDBZRQ1: Automotive Catalog Adjustable Precision Shunt Regulator, 34 ppm / degC, 100 mA, -40 to 125 degC, 3-pin SOT-23 (DBZ), Green (RoHS & no Sb/Br); Manufacturer: Texas Instruments; Alternate PartNumber: Equivalent; Initial Accuracy @ 25/deg C(%): 1; Iout/Iz(Max)(mA): 100; Min Iz for Regulation(uA): 600; SubFamily: Shunt Voltage Reference; Temp Coeff(Typ)(ppm/ degree C): 34; VO Adj(Max)(V): 36; VO Adj(Min)(V): 2.495
U6 = CMP-0083997-1: 4-A, 6-A, 5.7-kVRMS Isolated Dual-Channel Gate Driver with Enable, DWK0014A (SOIC-14); Alternate PartNumber: UCC21530QDWKQ1; Alternate Manufacturer: Texas Instruments; SizeAreaWB_mm2: 151.29; SizeZ_mm: 2.65; SizeX_mm: 10.3; SizeArea_mm2: 106.09; CompType: IC; AEC Qualified: Y; AEC Category: Q200
U7 = CMP-0077719-1: Automotive, High Speed, Robust EMC Reinforced Dual-Channel Digital Isolator, D0008B (SOIC-8); Alternate Manufacturer: Texas Instruments; SizeAreaWB_mm2: 55.2; SizeZ_mm: 1.75; SizeX_mm: 6.0; SizeY_mm: 4.9; SizeArea_mm2: 29.4; CompType: IC; AEC Qualified: Y; AEC Category: Q200
U8 = LMV762QMA: Automotive Low Voltage, Precision Comparator with Push-Pull Output, D0008A; Manufacturer: Texas Instruments; CompType: OpAmp IC

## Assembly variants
001: not fitted C23 C23 C24 C24 C39 C39 C40 C40 FID1 FID2 FID3 R31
